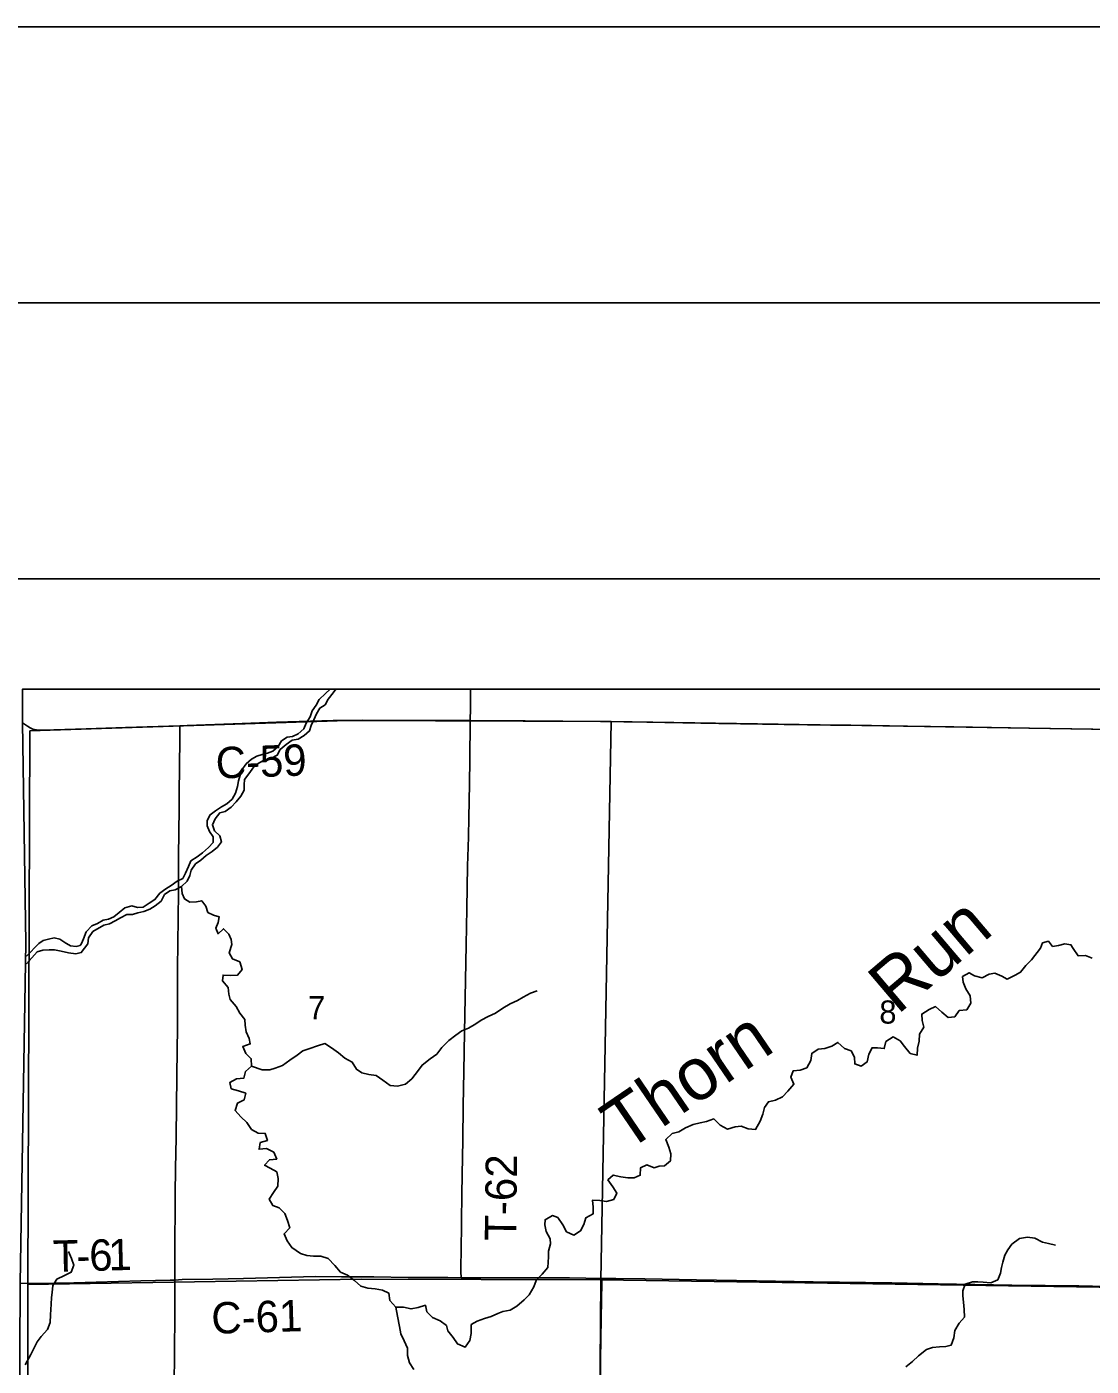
# Model space of a CAD drawing. Extents: x 0 to 34, y 0 to 22.
# Drawn here: x 2.992 to 4.92, y 19.573 to 22 of the extents above; entities that cross this region are included whole.
import ezdxf

# ---------------------------------------------------------------- set-up
doc = ezdxf.new("R2010")
doc.units = 0
for name, color, linetype in [('Default', 7, 'Continuous'), ('GM_X_City_Street', 7, 'Continuous'), ('GM_X_County_Road_Text', 7, 'Continuous'), ('GM_X_Interchange_Ramps', 7, 'Continuous'), ('GM_X_Major_River_Text', 7, 'Continuous'), ('GM_X_Minor_River', 7, 'Continuous'), ('GM_X_Minor_River_Text', 7, 'Continuous'), ('GM_X_Section', 7, 'Continuous'), ('GM_X_Unincorporated_Location', 7, 'Continuous'), ('SH_Cut_Line', 7, 'Continuous'), ('SH_Data', 7, 'Continuous'), ('SH_Text', 7, 'Continuous')]:
    doc.layers.add(name, color=color, linetype=linetype)

msp = doc.modelspace()

# ---------------------------------------------------------------- linework, layer by layer
at = {"layer": 'Default'}
msp.add_lwpolyline([(8.1282, 20.8), (2.9842, 20.8), (2.984, 20.7397), (2.9904, 20.3395), (2.9796, 19.7242), (2.9753, 18.7199), (2.9708, 17.6769), (2.9623, 15.7101)], dxfattribs=at)
at = {"layer": 'GM_X_City_Street'}
for points in [[(2.9842, 20.7391), (2.9933, 20.7327), (2.998, 20.7298), (3.0028, 20.7277), (3.0094, 20.7263), (3.0216, 20.7257), (3.0993, 20.7282), (3.1707, 20.7304), (3.2689, 20.7337)], [(3.2689, 20.7337), (3.2825, 20.7341), (3.3819, 20.7376), (3.444, 20.74), (3.5466, 20.7431), (3.5994, 20.7438), (3.6926, 20.7432), (3.7486, 20.7432), (3.7953, 20.743)], [(3.7953, 20.743), (3.8947, 20.7428), (4.0314, 20.7415), (4.1153, 20.7402), (4.2456, 20.738), (4.3637, 20.7359), (4.4476, 20.7347), (4.4849, 20.7344), (4.5222, 20.7338), (4.5875, 20.7327), (4.6714, 20.7316), (4.7397, 20.7306), (4.8081, 20.7293), (4.9231, 20.7277), (5.0691, 20.7246), (5.0748, 20.7246)], [(3.2599, 19.7293), (3.2734, 19.7301), (3.3287, 19.731), (3.3847, 19.732), (3.4282, 19.7331), (3.5151, 19.7355), (3.5617, 19.7351), (3.6207, 19.7349), (3.6829, 19.7341), (3.7295, 19.7341), (3.7543, 19.7338), (3.7787, 19.7336)], [(3.7787, 19.7336), (3.8009, 19.7333), (3.8599, 19.7333), (3.9252, 19.7331), (3.9749, 19.7331), (4.0339, 19.7324)], [(4.0339, 19.7324), (4.0588, 19.7321), (4.1116, 19.7314), (4.2048, 19.7299), (4.3135, 19.728), (4.4161, 19.7264), (4.559, 19.7241), (4.6428, 19.7226), (4.7764, 19.7203), (4.8976, 19.7188), (4.997, 19.7167), (5.056, 19.7161)]]:
    msp.add_lwpolyline(points, dxfattribs=at)
at = {"layer": 'GM_X_Interchange_Ramps'}
for points in [[(3.7953, 20.743), (3.7955, 20.7653), (3.7955, 20.7808), (3.7955, 20.7972), (3.7955, 20.8)], [(3.2599, 19.7293), (3.2602, 19.7746), (3.2609, 19.8834), (3.2611, 19.9331), (3.2616, 19.958), (3.2624, 19.989), (3.263, 20.0449), (3.2636, 20.0978), (3.2642, 20.1475), (3.2646, 20.1848), (3.2647, 20.2469), (3.2651, 20.2904), (3.2652, 20.3432), (3.2659, 20.3805), (3.2665, 20.4364), (3.2666, 20.4613), (3.2669, 20.4923), (3.2676, 20.5452), (3.268, 20.5793), (3.2681, 20.6197), (3.2684, 20.6508), (3.269, 20.7191), (3.2689, 20.7285), (3.2689, 20.7337)], [(3.7918, 20.5327), (3.7927, 20.5666), (3.7938, 20.6287), (3.7942, 20.6722), (3.7952, 20.7405), (3.7953, 20.743)], [(3.7786, 19.7774), (3.7793, 19.8369), (3.7801, 19.8835), (3.7806, 19.9207), (3.7816, 19.9828), (3.7825, 20.0449), (3.7838, 20.107), (3.7849, 20.1785), (3.7859, 20.2406), (3.7875, 20.3368), (3.789, 20.402), (3.7903, 20.4797), (3.7913, 20.5138), (3.7918, 20.5327)], [(3.7787, 19.7336), (3.7785, 19.7375), (3.7784, 19.7406), (3.7784, 19.7592), (3.7786, 19.7774)], [(3.2599, 19.7293), (3.2734, 19.7301), (3.3287, 19.731), (3.3847, 19.732), (3.4282, 19.7331), (3.5151, 19.7355), (3.5617, 19.7351), (3.6207, 19.7349), (3.6829, 19.7341), (3.7295, 19.7341), (3.7543, 19.7338), (3.7787, 19.7336)], [(3.7787, 19.7336), (3.8009, 19.7333), (3.8599, 19.7333), (3.9252, 19.7331), (3.9749, 19.7331), (4.0339, 19.7324)], [(4.0274, 18.7218), (4.0275, 18.7368), (4.027, 18.8052), (4.0264, 18.8767), (4.0262, 19.0228), (4.0262, 19.0726), (4.0257, 19.1099), (4.026, 19.1316), (4.026, 19.1502), (4.0258, 19.1627), (4.0256, 19.1875), (4.0265, 19.2248), (4.0265, 19.2282), (4.0267, 19.2559), (4.0271, 19.2963), (4.0281, 19.3584), (4.0285, 19.3989), (4.0298, 19.4672), (4.0313, 19.5854), (4.0325, 19.66), (4.0338, 19.7253), (4.0339, 19.7324)], [(4.0339, 19.7324), (4.0588, 19.7321), (4.1116, 19.7314), (4.2048, 19.7299), (4.3135, 19.728), (4.4161, 19.7264), (4.559, 19.7241), (4.6428, 19.7226), (4.7764, 19.7203), (4.8976, 19.7188), (4.997, 19.7167), (5.056, 19.7161)], [(2.9798, 19.7237), (3.0111, 19.7234), (3.0768, 19.7245), (3.1986, 19.7278), (3.2517, 19.7291), (3.2599, 19.7293)], [(3.2571, 19.2226), (3.2573, 19.2619), (3.2575, 19.3241), (3.2579, 19.3707), (3.2582, 19.4111), (3.2586, 19.4919), (3.2588, 19.5385), (3.2594, 19.5975), (3.2598, 19.669), (3.2599, 19.7187), (3.2599, 19.7293)]]:
    msp.add_lwpolyline(points, dxfattribs=at)
at = {"layer": 'GM_X_Section'}
for points in [[(3.5414, 20.8), (3.5331, 20.7918), (3.5218, 20.7811), (3.5159, 20.771), (3.5088, 20.7609), (3.505, 20.75), (3.4979, 20.7381), (3.4935, 20.7283), (3.4834, 20.7187), (3.4734, 20.7141), (3.4635, 20.7128), (3.4531, 20.7063), (3.4475, 20.6958), (3.4378, 20.6873), (3.4282, 20.6842), (3.418, 20.6818), (3.4084, 20.6786), (3.3988, 20.6728), (3.3891, 20.6644), (3.3816, 20.6539), (3.3783, 20.6441), (3.3754, 20.634), (3.3736, 20.6238), (3.3702, 20.6113), (3.3638, 20.6009), (3.3541, 20.592), (3.3445, 20.5866), (3.3337, 20.5793), (3.324, 20.5723), (3.3188, 20.5618), (3.3186, 20.5524), (3.3228, 20.542), (3.3297, 20.5323), (3.3295, 20.5224), (3.3209, 20.5128), (3.3104, 20.5032), (3.3007, 20.4962), (3.2892, 20.4886), (3.2847, 20.4788), (3.2791, 20.4668), (3.2743, 20.4571), (3.2643, 20.4521), (3.2535, 20.4444), (3.2435, 20.4382), (3.2326, 20.4301), (3.224, 20.4186), (3.2136, 20.4121), (3.2024, 20.4048), (3.1925, 20.4043), (3.1824, 20.4076), (3.1694, 20.4038), (3.159, 20.3953), (3.1493, 20.3873), (3.1397, 20.3833), (3.1302, 20.3813), (3.1202, 20.3755), (3.1098, 20.3709), (3.0993, 20.3602), (3.0948, 20.3474), (3.0912, 20.3389)], [(3.1024, 20.3388), (3.1035, 20.3494), (3.1114, 20.3606), (3.1314, 20.3722), (3.1417, 20.3746), (3.1517, 20.3804), (3.1617, 20.3858), (3.1733, 20.3919), (3.1835, 20.3916), (3.193, 20.3948), (3.2041, 20.3971), (3.2148, 20.4014), (3.2244, 20.4076), (3.2353, 20.416), (3.2413, 20.4276), (3.2509, 20.4346), (3.2608, 20.4366), (3.2724, 20.4423), (3.2821, 20.4519), (3.2873, 20.4621), (3.2895, 20.4719), (3.2973, 20.4834), (3.3074, 20.4904), (3.3171, 20.4985), (3.3275, 20.5061), (3.3372, 20.5138), (3.3443, 20.5235), (3.3415, 20.5342), (3.3319, 20.5432), (3.3281, 20.5544), (3.3329, 20.5652), (3.3415, 20.5756), (3.3515, 20.578), (3.3619, 20.5861), (3.3713, 20.5957), (3.3795, 20.6061), (3.3859, 20.617), (3.3857, 20.6265), (3.3864, 20.6363), (3.3939, 20.6467), (3.4029, 20.659), (3.4126, 20.6667), (3.423, 20.6718), (3.434, 20.6741), (3.4456, 20.6803), (3.4511, 20.6904), (3.4616, 20.6999), (3.4728, 20.7076), (3.4835, 20.7092), (3.4943, 20.7158), (3.5043, 20.7242), (3.5073, 20.734), (3.5117, 20.7445), (3.5169, 20.755), (3.5229, 20.7655), (3.5325, 20.7717), (3.5381, 20.7818), (3.5468, 20.7933), (3.5517, 20.8)], [(3.2724, 20.4423), (3.2731, 20.4298), (3.2778, 20.4198), (3.2875, 20.4142), (3.2992, 20.4146), (3.3088, 20.4166), (3.3161, 20.4066), (3.3199, 20.3954), (3.33, 20.3902), (3.3405, 20.3873), (3.3383, 20.3774), (3.3343, 20.3669), (3.3385, 20.3569), (3.3483, 20.3658), (3.3578, 20.356), (3.3621, 20.3464), (3.3633, 20.3376)], [(2.9912, 20.3023), (3.0108, 20.324), (3.021, 20.3271), (3.0324, 20.3275), (3.0419, 20.3276), (3.054, 20.3253), (3.0677, 20.322), (3.0806, 20.3205), (3.0904, 20.3228), (3.1024, 20.3388)], [(3.0139, 20.3392), (2.9913, 20.3162)], [(3.0636, 20.339), (3.0624, 20.3399), (3.0516, 20.3467), (3.0414, 20.3492), (3.0311, 20.3469), (3.0216, 20.3445), (3.0139, 20.3392)], [(3.0912, 20.3389), (3.0883, 20.3353), (3.0811, 20.3339), (3.071, 20.335), (3.0636, 20.339)], [(3.3633, 20.3376), (3.3586, 20.3222), (3.3647, 20.3112), (3.3777, 20.3056), (3.3819, 20.2923), (3.3736, 20.282), (3.3611, 20.2812), (3.3474, 20.2819), (3.3463, 20.2713), (3.3566, 20.2596), (3.3581, 20.2471), (3.3605, 20.2376), (3.3711, 20.2247), (3.3776, 20.213), (3.3871, 20.2013), (3.3876, 20.1914), (3.3891, 20.1789), (3.3948, 20.1668), (3.3968, 20.1573), (3.3831, 20.1527), (3.3885, 20.1399), (3.3984, 20.1304), (3.3992, 20.1168), (3.3879, 20.1072), (3.3849, 20.0951), (3.3716, 20.0939), (3.3599, 20.0874), (3.3622, 20.076), (3.3751, 20.0723), (3.3884, 20.0678), (3.3854, 20.0556), (3.3733, 20.0499), (3.3691, 20.0366), (3.3794, 20.0253), (3.3905, 20.0151), (3.3992, 20.0022), (3.411, 19.9954), (3.4239, 19.9951), (3.4277, 19.9822), (3.4149, 19.9784), (3.4126, 19.9662), (3.4259, 19.9678), (3.4392, 19.961), (3.4446, 19.9485), (3.4313, 19.9473), (3.4226, 19.9374), (3.4329, 19.9322), (3.4446, 19.9254), (3.4473, 19.9133), (3.4466, 19.8996), (3.4387, 19.8878), (3.4308, 19.8757), (3.4373, 19.8647), (3.449, 19.8602), (3.4593, 19.85), (3.4639, 19.8371), (3.4681, 19.8242), (3.4579, 19.8132), (3.4633, 19.8007), (3.4717, 19.7882), (3.4877, 19.7776), (3.499, 19.7739), (3.5112, 19.7728), (3.5245, 19.7724), (3.5381, 19.7683), (3.5499, 19.7558), (3.5602, 19.7434), (3.5728, 19.7381), (3.5857, 19.7283), (3.5967, 19.7184), (3.6096, 19.7147), (3.6229, 19.7132), (3.6362, 19.711), (3.648, 19.7053), (3.6496, 19.6925), (3.6606, 19.68), (3.6743, 19.68), (3.6879, 19.677), (3.7008, 19.6797), (3.7141, 19.6836), (3.7164, 19.6718), (3.7271, 19.6616), (3.7404, 19.6556), (3.7521, 19.6469), (3.7548, 19.6374), (3.764, 19.6253), (3.772, 19.614), (3.7861, 19.608), (3.7944, 19.6201), (3.7966, 19.6327), (3.7969, 19.6486), (3.8075, 19.6551), (3.8208, 19.66), (3.8333, 19.6631), (3.845, 19.6688), (3.8545, 19.6723), (3.8674, 19.675), (3.8795, 19.6822), (3.8927, 19.6933), (3.9022, 19.7028), (3.9105, 19.7169)], [(4.8282, 20.3305), (4.8321, 20.3402), (4.8424, 20.3433), (4.8501, 20.3336), (4.8608, 20.3352), (4.8722, 20.3387), (4.8832, 20.3369), (4.8874, 20.3303)], [(4.6732, 20.2061), (4.6811, 20.2175), (4.6947, 20.219), (4.7019, 20.2312), (4.7007, 20.2445), (4.6927, 20.2569), (4.6881, 20.2691), (4.6866, 20.2793), (4.6991, 20.2862), (4.7089, 20.2805), (4.7226, 20.2771), (4.7355, 20.2833), (4.7453, 20.2852), (4.7583, 20.2799), (4.7681, 20.2746), (4.7821, 20.2819), (4.792, 20.2869), (4.8014, 20.299), (4.812, 20.3093), (4.8282, 20.3305)], [(4.8874, 20.3303), (4.8962, 20.3168), (4.9099, 20.3176), (4.9216, 20.3127)], [(3.3992, 20.1168), (3.4182, 20.11), (3.4322, 20.11), (3.4421, 20.1131), (3.4553, 20.1181), (3.4686, 20.1276), (3.4814, 20.1368), (3.4917, 20.1444), (3.5049, 20.149), (3.5186, 20.1536), (3.5318, 20.1578), (3.544, 20.1502), (3.5565, 20.1408), (3.5683, 20.1314), (3.5813, 20.1242), (3.5893, 20.1113), (3.5988, 20.1049), (3.6117, 20.1015), (3.6246, 20.1001), (3.6371, 20.0918), (3.6501, 20.0816), (3.6637, 20.0809), (3.6781, 20.0843), (3.6891, 20.0942), (3.7016, 20.1094), (3.708, 20.1189), (3.7227, 20.1304), (3.7345, 20.1387), (3.7435, 20.1505), (3.7564, 20.1631), (3.7689, 20.173), (3.7798, 20.181), (3.792, 20.186), (3.8052, 20.1936), (3.8151, 20.2005), (3.8276, 20.207), (3.8412, 20.2131), (3.8541, 20.2218), (3.8677, 20.2298), (3.8809, 20.2356), (3.8912, 20.2417), (3.9044, 20.2489), (3.9165, 20.2535)], [(3.9105, 19.7169), (3.9146, 19.7286), (3.9252, 19.74), (3.9358, 19.7522), (3.9365, 19.7617), (3.9368, 19.7716), (3.9368, 19.7818), (3.9406, 19.7947), (3.9398, 19.8042), (3.9325, 19.8171), (3.9302, 19.8292), (3.9309, 19.8387), (3.9442, 19.8463), (3.9537, 19.8425), (3.9628, 19.8297), (3.9697, 19.8168), (3.983, 19.8104), (3.9951, 19.8184), (4.0007, 19.8302), (4.0045, 19.8423), (4.0177, 19.8492), (4.0177, 19.8617), (4.0169, 19.8742), (4.0302, 19.8735), (4.0423, 19.8717), (4.0552, 19.8751), (4.0605, 19.8865), (4.0536, 19.8983), (4.0445, 19.9107), (4.0543, 19.9195), (4.068, 19.9165), (4.0805, 19.9147), (4.0923, 19.9143), (4.1032, 19.9193), (4.1036, 19.9326), (4.1153, 19.9379), (4.1282, 19.9326), (4.1377, 19.9357), (4.1472, 19.9361), (4.1578, 19.9453), (4.1585, 19.9582), (4.1547, 19.9703), (4.1493, 19.9843), (4.161, 19.995), (4.1731, 19.998), (4.1849, 20.0053), (4.1993, 20.011), (4.2114, 20.0141), (4.2232, 20.0164), (4.2364, 20.0214), (4.2482, 20.01), (4.2611, 20.0029), (4.2752, 20.0067), (4.2862, 20.0083), (4.2987, 20.0034), (4.312, 20.0023), (4.3206, 20.0171), (4.3255, 20.0297), (4.3285, 20.0422), (4.3353, 20.0524), (4.3482, 20.0555), (4.3607, 20.0613), (4.3705, 20.0715), (4.3815, 20.0841), (4.3758, 20.097), (4.3799, 20.1083), (4.3928, 20.1095), (4.4049, 20.1141), (4.4121, 20.127), (4.4139, 20.1399), (4.4253, 20.1479), (4.4378, 20.1487), (4.4499, 20.1533), (4.4613, 20.1598), (4.4731, 20.1489), (4.4852, 20.1444), (4.491, 20.1334), (4.4918, 20.1209), (4.5035, 20.1167), (4.5141, 20.1247), (4.5175, 20.1384), (4.5231, 20.1502), (4.533, 20.1502), (4.5451, 20.1487), (4.5478, 20.1613), (4.561, 20.17), (4.5739, 20.1629), (4.5819, 20.1523), (4.5922, 20.1398), (4.6047, 20.1368), (4.6051, 20.1497), (4.6085, 20.1622), (4.6088, 20.1751), (4.6171, 20.1873), (4.614, 20.1994), (4.6132, 20.2112), (4.6265, 20.2195), (4.6382, 20.2249), (4.6492, 20.2147), (4.661, 20.2053), (4.6732, 20.2061)], [(4.584, 19.5724), (4.5961, 19.5815), (4.6074, 19.5922), (4.6218, 19.6036), (4.6328, 19.6074), (4.6453, 19.6086), (4.6567, 19.6087), (4.6665, 19.6114), (4.6714, 19.6246), (4.6729, 19.6379), (4.6808, 19.6512), (4.6903, 19.6623), (4.6902, 19.6763), (4.689, 19.6892), (4.6878, 19.7005), (4.6878, 19.71), (4.6919, 19.7222), (4.7048, 19.726), (4.7147, 19.7261), (4.7246, 19.7253), (4.7382, 19.7242), (4.7507, 19.7296), (4.756, 19.7421), (4.7578, 19.7524), (4.7597, 19.7619), (4.7635, 19.7744), (4.7691, 19.7839), (4.7763, 19.7945), (4.7903, 19.8048), (4.8047, 19.8071), (4.818, 19.8053), (4.832, 19.7981), (4.8427, 19.7955), (4.8556, 19.7925)], [(2.9892, 19.5756), (2.9989, 19.5947), (3.0046, 19.6053), (3.0106, 19.6175), (3.0178, 19.627), (3.0291, 19.6395), (3.034, 19.6525), (3.0351, 19.6661), (3.0358, 19.6858), (3.0369, 19.6976), (3.038, 19.7071), (3.0391, 19.7196), (3.0466, 19.731), (3.0603, 19.7379), (3.0724, 19.7436), (3.0769, 19.7561), (3.0731, 19.7686), (3.0677, 19.7808)], [(3.6606, 19.68), (3.6633, 19.6641), (3.6672, 19.6451), (3.6695, 19.6318), (3.6752, 19.6193), (3.6814, 19.6061), (3.6818, 19.5924), (3.6849, 19.5796), (3.6929, 19.5671)]]:
    msp.add_lwpolyline(points, dxfattribs=at)
at = {"layer": 'GM_X_Unincorporated_Location'}
for points in [[(2.9973, 20.7247), (3.5729, 20.7431), (4.0503, 20.7412), (4.0319, 19.7295), (3.5973, 19.7312), (2.9937, 19.7212)], [(4.0503, 20.7412), (5.0724, 20.7252), (5.0575, 19.7147), (4.0319, 19.7295)], [(2.9937, 19.7212), (3.5973, 19.7312), (4.0319, 19.7295), (4.0237, 18.7217), (3.4868, 18.7265), (2.9925, 18.7172)], [(4.0319, 19.7295), (5.0575, 19.7147), (5.0466, 18.7043), (4.0237, 18.7217)]]:
    msp.add_lwpolyline(points, close=True, dxfattribs=at)
at = {"layer": 'SH_Cut_Line'}
msp.add_line((2, 21), (9, 21), dxfattribs=at)
at = {"layer": 'SH_Data'}
msp.add_lwpolyline([(1.5, 21.5), (33.5, 21.5), (33.5, 0.5), (1.5, 0.5)], close=True, dxfattribs=at)
at = {"layer": 'SH_Text'}
for points in [[(0, 0), (34, 0), (34, 22), (0, 22)], [(2.9377, 14), (8.8, 14), (8.8, 20.8), (2.9842, 20.8), (2.984, 20.7397), (2.9904, 20.3395), (2.9796, 19.7242), (2.9753, 18.7199), (2.9708, 17.6769), (2.9623, 15.7101), (2.9479, 14.7065)]]:
    msp.add_lwpolyline(points, close=True, dxfattribs=at)

# ---------------------------------------------------------------- texts
at = {"layer": 'GM_X_County_Road_Text'}
for s, height, rotation, p in [('T-62', 0.05682, 89.2934, (3.8782, 19.8004)), ('6', 0.0568, 1.497, (3.1056, 19.7457)), ('1', 0.0568, 1.5109, (3.1403, 19.7466)), ('T', 0.0568, 1.1218, (3.0396, 19.7443)), ('-', 0.0568, 1.3943, (3.0823, 19.7451))]:
    msp.add_text(s, height=height, rotation=rotation, dxfattribs=at).set_placement(p)
at = {"layer": 'GM_X_Major_River_Text'}
for s, p in [('7', (3.5016, 20.202)), ('8', (4.5362, 20.194))]:
    msp.add_text(s, height=0.0419, rotation=0, dxfattribs=at).set_placement(p)
at = {"layer": 'GM_X_Minor_River'}
for s, rotation, p in [('Run', 40.3115, (4.5688, 20.2086)), ('Thorn', 34.3127, (4.0768, 19.9597))]:
    msp.add_text(s, height=0.09472, rotation=rotation, dxfattribs=at).set_placement(p)
at = {"layer": 'GM_X_Minor_River_Text'}
for s, rotation, p in [('C-59', 2.0669, (3.3351, 20.6378)), ('C-61', 1.7185, (3.327, 19.6319))]:
    msp.add_text(s, height=0.05682, rotation=rotation, dxfattribs=at).set_placement(p)

doc.saveas('drawing.dxf')
